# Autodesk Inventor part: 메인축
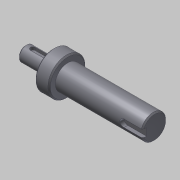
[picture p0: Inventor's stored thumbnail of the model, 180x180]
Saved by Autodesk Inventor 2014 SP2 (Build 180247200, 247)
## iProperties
Created: 2018-09
Part Number: 메인축
Document SubType Name: Modeling
Density: 1 g/cm^3
Material: 강철, 연강
Appearance: 강철
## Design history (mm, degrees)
sketch "스케치1"
  geometry: L1 (34.997, -37.5)-(34.997, -77.5) reference; L2 (46.5, -38.401)-(46.5, -76.599) reference; L3 (12.497, -57.5)-(116.5, -57.5); L4 (12.497, -63.5)-(34.997, -63.5); L5 (34.997, -72.5)-(46.5, -72.5); L6 (46.5, -67.5)-(116.5, -67.5); L7 (116.5, -67.5)-(116.5, -57.5); L8 (12.497, -63.5)-(12.497, -57.5); 2 further points
  constraints: 12 end point, 5 point on line, 4 perpendicular, 1 midpoint, 1 parallel
  dimensions: "d0" = 20 diameter of L6 L3; "d1" = 30 diameter of L5 L3; "d2" = 22.5 distance of L4.start L4.end; "d3" = 70 distance of L6.start L6.end; "d5" = 12 diameter of L4 L3
revolve "회전1" sketch "스케치1" stored, may be unused: angle "d4" = 90 deg
chamfer "모따기1" distance "d6" = 1; stored, may be unused: second distance "d7" = 2, angle "d8" = 45 deg
node "작업 평면1"
sketch "스케치2"
  geometry: L1 (-11.25, -5)-(-11.25, 5) reference; L2 (-5.25, 2)-(4.75, 2); L3 (4.75, -2)-(-5.25, -2); A1 r 2 centre (4.75, 0) between (4.75, -2) and (4.75, 2); A2 r 2 centre (-5.25, 0) between (-5.25, 2) and (-5.25, -2); 2 further points
  constraints: 4 end point, 4 point on circle, 4 tangent, 2 centre point, 1 horizontal alignment, 1 midpoint, 1 parallel, 1 perpendicular
  dimensions: "d9" = 4 distance between parallel lines of L3 L2; "d10" = 14 dimension on A1 A2; "d11" = 4 distance edge to line of A2 L1
extrude "돌출1" cut sketch "스케치2" distance "d12" = 2.5; taper "d13" = 0 deg
node "작업 평면2"
sketch "스케치3"
  geometry: L1 (35, 9)-(35, -9) reference; L2 (35, 3)-(20, 3); L3 (20, -3)-(35, -3); A1 r 3 centre (20, 0) between (20, 3) and (20, -3); 2 further points
  constraints: 4 end point, 2 perpendicular, 2 point on circle, 2 point on line, 2 tangent, 1 centre point, 1 horizontal alignment, 1 midpoint
  dimensions: "d14" = 6 distance between parallel lines of L3 L2; "d15" = 18 dimension on A1 L1
extrude "돌출2" cut sketch "스케치3" distance "d16" = 3.5; taper "d17" = 0 deg
node "솔리드1"
node "참조1"
node "참조2"
